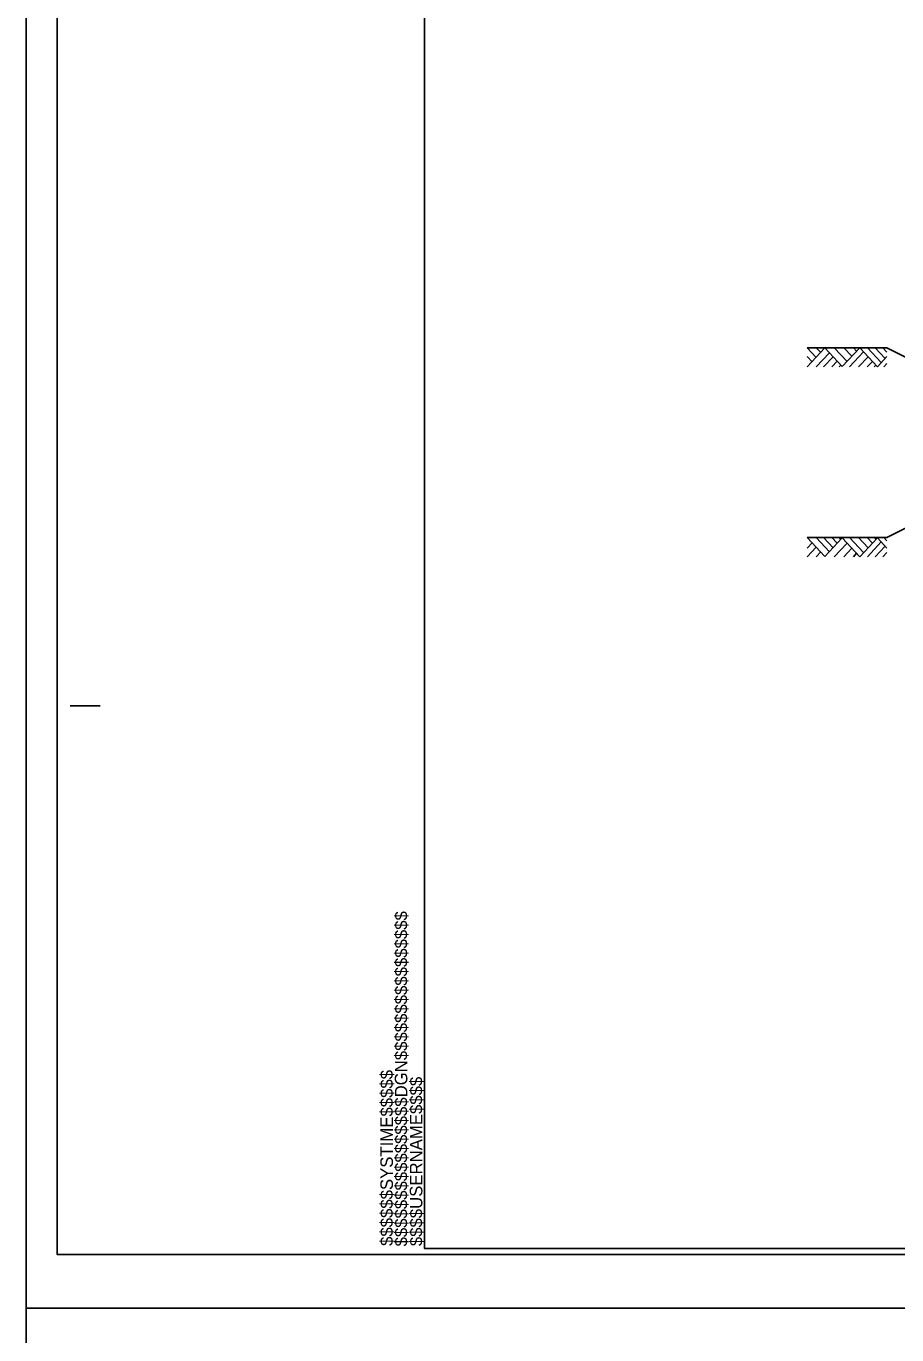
# Model space of a CAD drawing. Extents: x 1901670 to 1902225, y 193498 to 194278.
# Drawn here: x 1901965.8 to 1902002.4, y 194046.9 to 194101.8 of the extents above; entities that cross this region are included whole.
import ezdxf

# ---------------------------------------------------------------- set-up
doc = ezdxf.new("R2010")
doc.units = 0
for name, color, linetype in [('Old_Level_1', 7, 'Continuous'), ('Sheet Border Standard 30in CELL', 7, 'Continuous'), ('Sheet Cutting Line CELL', 7, 'Continuous'), ('Sheet Plot Border Inside CELL', 7, 'Continuous'), ('Sheet Plot Border Outside CELL', 7, 'Continuous'), ('Typical Pavement Slope CELL', 7, 'Continuous')]:
    doc.layers.add(name, color=color, linetype=linetype)

msp = doc.modelspace()

# ---------------------------------------------------------------- linework, layer by layer
at = {"layer": 'Old_Level_1'}
for p, q in [((1901998.601, 194088.277), (1901998.976, 194087.874)), ((1901998.601, 194087.472), (1901999.343, 194088.269)), ((1901998.975, 194087.472), (1901999.529, 194088.068)), ((1901998.976, 194088.277), (1901999.163, 194088.076)), ((1901999.343, 194088.269), (1902000.067, 194087.49)), ((1901999.734, 194088.277), (1902000.267, 194087.704)), ((1902000.067, 194087.49), (1902000.798, 194088.276)), ((1902000.132, 194088.277), (1902000.465, 194087.918)), ((1902000.377, 194087.472), (1902000.963, 194088.1)), ((1902000.534, 194088.277), (1902000.667, 194088.134)), ((1902000.798, 194088.276), (1902001.539, 194087.48)), ((1902001.12, 194088.277), (1902001.7, 194087.654)), ((1902001.453, 194088.277), (1902001.867, 194087.833)), ((1902001.773, 194088.277), (1902001.943, 194088.094)), ((1901998.601, 194087.915), (1901998.807, 194087.693)), ((1901999.284, 194087.472), (1901999.685, 194087.901)), ((1901999.631, 194087.472), (1901999.858, 194087.715)), ((1901999.942, 194087.472), (1902000.013, 194087.548)), ((1902000.747, 194087.472), (1902001.147, 194087.901)), ((1902001.113, 194087.472), (1902001.33, 194087.705)), ((1902001.408, 194087.472), (1902001.477, 194087.546)), ((1902001.539, 194087.48), (1902001.943, 194087.915)), ((1902001.809, 194087.472), (1902001.943, 194087.615)), ((1901998.601, 194080.32), (1901999.343, 194079.523)), ((1901998.601, 194079.877), (1901998.807, 194080.099)), ((1901998.601, 194079.515), (1901998.976, 194079.918)), ((1901998.975, 194080.32), (1901999.529, 194079.724)), ((1901999.284, 194080.32), (1901999.685, 194079.891)), ((1901999.343, 194079.523), (1902000.067, 194080.302)), ((1901999.631, 194080.32), (1901999.858, 194080.077)), ((1901999.734, 194079.515), (1902000.267, 194080.088)), ((1901999.942, 194080.32), (1902000.013, 194080.244)), ((1902000.067, 194080.302), (1902000.798, 194079.516)), ((1902000.132, 194079.515), (1902000.465, 194079.874)), ((1902000.377, 194080.32), (1902000.963, 194079.692)), ((1902000.747, 194080.32), (1902001.147, 194079.891)), ((1902000.798, 194079.516), (1902001.539, 194080.312)), ((1902001.113, 194080.32), (1902001.33, 194080.087)), ((1902001.12, 194079.515), (1902001.7, 194080.138)), ((1902001.408, 194080.32), (1902001.477, 194080.246)), ((1902001.453, 194079.515), (1902001.867, 194079.959)), ((1902001.539, 194080.312), (1902001.943, 194079.877)), ((1902001.809, 194080.32), (1902001.943, 194080.177)), ((1901998.976, 194079.515), (1901999.163, 194079.716)), ((1902000.534, 194079.515), (1902000.667, 194079.658)), ((1902001.773, 194079.515), (1902001.943, 194079.698))]:
    msp.add_line(p, q, dxfattribs=at)
at = {"layer": 'Sheet Border Standard 30in CELL'}
msp.add_line((1901967.694, 194073.264), (1901968.944, 194073.264), dxfattribs=at)
msp.add_lwpolyline([(1902132.544, 194155.514), (1901982.544, 194155.514), (1901982.544, 194050.514), (1902132.544, 194050.514)], close=True, dxfattribs=at)
at = {"layer": 'Sheet Cutting Line CELL'}
for p, q in [((1901965.844, 194158.014), (1901965.844, 194048.014)), ((1901965.844, 194048.014), (1902134.244, 194048.014)), ((1902134.244, 194048.014), (1901965.844, 194048.014)), ((1901965.844, 194048.014), (1901965.844, 193938.014))]:
    msp.add_line(p, q, dxfattribs=at)
at = {"layer": 'Sheet Plot Border Inside CELL'}
msp.add_lwpolyline([(1902133.794, 194155.769), (1901967.144, 194155.769), (1901967.144, 194050.259), (1902133.794, 194050.259)], close=True, dxfattribs=at)
at = {"layer": 'Sheet Plot Border Outside CELL'}
for points in [[(1902134.244, 194158.014), (1901965.844, 194158.014), (1901965.844, 194048.014), (1902134.244, 194048.014)], [(1902134.244, 194048.014), (1901965.844, 194048.014), (1901965.844, 193938.014), (1902134.244, 193938.014)]]:
    msp.add_lwpolyline(points, close=True, dxfattribs=at)
at = {"layer": 'Typical Pavement Slope CELL'}
for p in [(1902001.943, 194088.277), (1902001.943, 194080.32)]:
    msp.add_line(p, (1902009.9, 194084.298), dxfattribs=at)
for points in [[(1901998.601, 194088.277), (1902001.943, 194088.277)], [(1901998.601, 194080.32), (1902001.943, 194080.32)]]:
    msp.add_lwpolyline(points, dxfattribs=at)

# ---------------------------------------------------------------- texts
at = {"layer": 'Sheet Border Standard 30in CELL'}
for s, p in [('$$$$$$$$$$$$$$$$DGN$$$$$$$$$$$$$$$$', (1901981.829, 194050.599)), ('$$$$$$SYSTIME$$$$$', (1901981.224, 194050.619)), ('$$$$USERNAME$$$$', (1901982.459, 194050.609))]:
    msp.add_text(s, height=0.525, rotation=90, dxfattribs=at).set_placement(p)

doc.saveas('drawing.dxf')
